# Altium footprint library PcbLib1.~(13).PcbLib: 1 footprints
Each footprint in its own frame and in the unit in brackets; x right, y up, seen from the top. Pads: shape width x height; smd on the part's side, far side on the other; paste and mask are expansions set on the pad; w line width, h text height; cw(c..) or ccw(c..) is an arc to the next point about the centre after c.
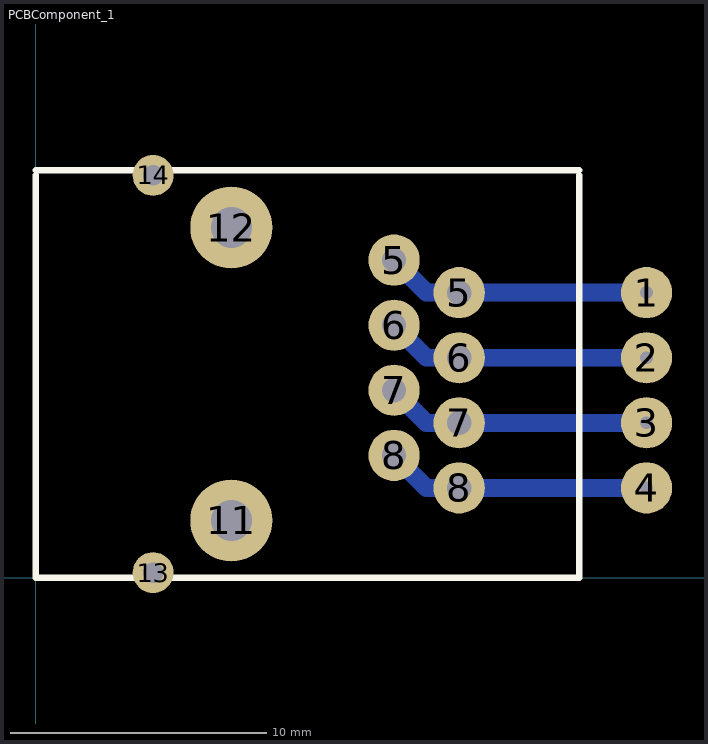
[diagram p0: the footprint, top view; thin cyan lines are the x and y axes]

## PCBComponent_1 [mm]
pads (16):
  round 2 hole 0.5: 1(23.825,11.125) 2(23.825,8.585) 3(23.825,6.045) 4(23.825,3.505)
  round 2 hole 0.95: 5(13.975,12.395) 5(16.515,11.125) 6(13.975,9.855) 6(16.515,8.585) 7(13.975,7.315) 7(16.515,6.045) 8(13.975,4.775) 8(16.515,3.505)
  round 3.2 hole 1.6: 11(7.625,2.235) 12(7.625,13.665)
  round 1.6 hole 0.8: 13(4.575,0.2) 14(4.575,15.7)
Bottom Layer:
  lines w0.7: 13.975,4.775 15.245,3.505 16.515,3.505 23.825,3.505 ; 13.975,7.315 15.245,6.045 16.515,6.045 23.825,6.045 ; 13.975,9.855 15.245,8.585 16.515,8.585 23.825,8.585 ; 13.975,12.395 15.245,11.125 16.515,11.125 23.825,11.125
Top Overlay:
  lines w0.254: 0,15.7 0,0 21.2,0 21.2,15.7 ; 0,15.9 21.2,15.9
